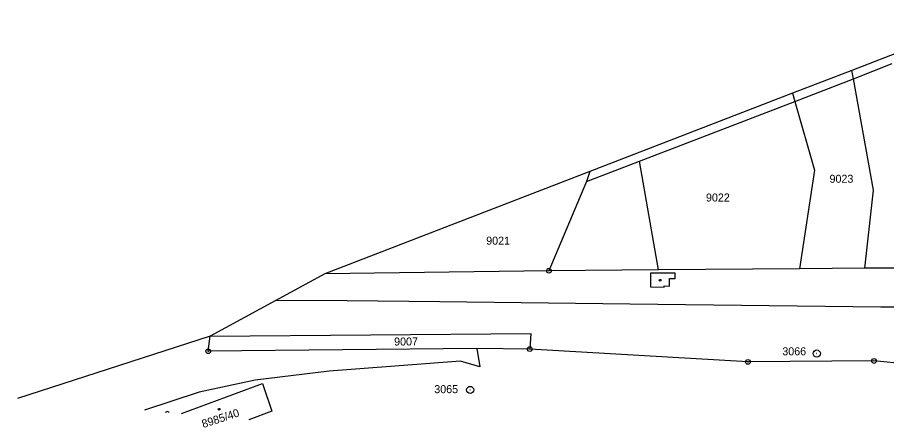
# Model space of a CAD drawing. Extents: x -825057 to -819383, y -1071633 to -1067888.
# Drawn here: x -825057.2 to -824872.6, y -1070106.1 to -1070019 of the extents above; entities that cross this region are included whole.
import ezdxf

# ---------------------------------------------------------------- set-up
doc = ezdxf.new("R2010")
doc.units = 0
for name, color, linetype in [('Vrstva 1', 7, 'Continuous'), ('Vrstva 10', 7, 'Continuous'), ('Vrstva 13', 7, 'Continuous'), ('Vrstva 17', 7, 'Continuous'), ('Vrstva 18', 7, 'Continuous'), ('Vrstva 19', 7, 'Continuous'), ('Vrstva 24', 7, 'Continuous'), ('Vrstva 25', 7, 'Continuous'), ('Vrstva 4', 7, 'Continuous')]:
    doc.layers.add(name, color=color, linetype=linetype)

msp = doc.modelspace()

# ---------------------------------------------------------------- linework, layer by layer
at = {"layer": 'Vrstva 1'}
for p, q in [((-824879.6, -1070032.03), (-824879.92, -1070030.25)), ((-824875.36, -1070055.66), (-824879.6, -1070032.03)), ((-824892.53, -1070035.09), (-824892.04, -1070036.81)), ((-824892.04, -1070036.81), (-824887.89, -1070051.42)), ((-824935.6, -1070051.67), (-824936.34, -1070053.81)), ((-824887.89, -1070051.42), (-824891.08, -1070072.35)), ((-824936.34, -1070053.81), (-824944.3, -1070072.78)), ((-824877.18, -1070072.24), (-824875.36, -1070055.66)), ((-824944.3, -1070072.78), (-824991.92, -1070073.41)), ((-824920.99, -1070072.59), (-824944.3, -1070072.78)), ((-824891.08, -1070072.35), (-824920.99, -1070072.59)), ((-824877.18, -1070072.24), (-824891.08, -1070072.35)), ((-824870.78, -1070072.19), (-824877.18, -1070072.24)), ((-825016.24, -1070086.67), (-824948.15, -1070086.08)), ((-824948.15, -1070086.08), (-824948.35, -1070089.4)), ((-825016.65, -1070089.86), (-825016.24, -1070086.67)), ((-824959.62, -1070089.3), (-825016.65, -1070089.86)), ((-824948.35, -1070089.4), (-824959.62, -1070089.3)), ((-824959.62, -1070089.3), (-824959, -1070093.16)), ((-824902.02, -1070092.13), (-824948.35, -1070089.4)), ((-824963.09, -1070091.99), (-824990.96, -1070094.07)), ((-824959, -1070093.16), (-824963.09, -1070091.99)), ((-824875.24, -1070091.93), (-824902.02, -1070092.13)), ((-824825.26, -1070096.77), (-824875.24, -1070091.93)), ((-824990.96, -1070094.07), (-825006.7, -1070095.98)), ((-825022.33, -1070103.09), (-825005.16, -1070096.71)), ((-825006.7, -1070095.98), (-825018.61, -1070098.58)), ((-825005.16, -1070096.71), (-825003.13, -1070102.57)), ((-825018.61, -1070098.58), (-825030.21, -1070102.38)), ((-825025.73, -1070102.78), (-825025.16, -1070102.57)), ((-825025.16, -1070102.57), (-825025.06, -1070102.84)), ((-825003.13, -1070102.57), (-825008.02, -1070104.39))]:
    msp.add_line(p, q, dxfattribs=at)
at = {"layer": 'Vrstva 10'}
for p, q in [((-824987.18, -1070079.15), (-825002.36, -1070079.1)), ((-824967.48, -1070079.36), (-824987.18, -1070079.15)), ((-824927.09, -1070079.84), (-824967.48, -1070079.36)), ((-824873.75, -1070080.47), (-824927.09, -1070079.84)), ((-824853.34, -1070080.66), (-824873.75, -1070080.47))]:
    msp.add_line(p, q, dxfattribs=at)
at = {"layer": 'Vrstva 13'}
for p, q in [((-824850.82, -1070018.98), (-824879.92, -1070030.25)), ((-824879.92, -1070030.25), (-824892.53, -1070035.09)), ((-824892.53, -1070035.09), (-824935.6, -1070051.67)), ((-824935.6, -1070051.67), (-824991.92, -1070073.41)), ((-824991.92, -1070073.41), (-825016.24, -1070086.67)), ((-825016.24, -1070086.67), (-825057.21, -1070099.92))]:
    msp.add_line(p, q, dxfattribs=at)
at = {"layer": 'Vrstva 24'}
for centre, radius in [((-824944.3, -1070072.78), 0.5), ((-824944.3, -1070072.78), 0.0327), ((-825016.65, -1070089.86), 0.5), ((-825016.65, -1070089.86), 0.0327), ((-824948.35, -1070089.4), 0.5), ((-824948.35, -1070089.4), 0.0327), ((-824887.38, -1070090.34), 0.75), ((-824902.02, -1070092.13), 0.5), ((-824887.38, -1070090.34), 0.0327), ((-824875.24, -1070091.93), 0.5), ((-824902.02, -1070092.13), 0.0327), ((-824875.24, -1070091.93), 0.0327), ((-824961.02, -1070098.06), 0.75), ((-824961.02, -1070098.06), 0.0327)]:
    msp.add_circle(centre, radius, dxfattribs=at)
at = {"layer": 'Vrstva 25'}
for centre in [(-824920.66, -1070074.78), (-825014.35, -1070102.16)]:
    msp.add_circle(centre, 0.175, dxfattribs=at)
at = {"layer": 'Vrstva 4'}
for p, q in [((-824879.6, -1070032.03), (-824871.35, -1070028.8)), ((-824892.04, -1070036.81), (-824879.6, -1070032.03)), ((-824925.04, -1070049.47), (-824892.04, -1070036.81)), ((-824936.34, -1070053.81), (-824925.04, -1070049.47)), ((-824920.99, -1070072.59), (-824925.04, -1070049.47)), ((-824922.68, -1070073.25), (-824922.71, -1070076.21)), ((-824917.48, -1070073.31), (-824922.68, -1070073.25)), ((-824918.67, -1070076.01), (-824918.65, -1070074.44)), ((-824918.65, -1070074.44), (-824917.49, -1070074.45)), ((-824917.49, -1070074.45), (-824917.48, -1070073.31)), ((-824922.71, -1070076.21), (-824919.8, -1070076.24)), ((-824919.8, -1070076.24), (-824919.8, -1070075.99)), ((-824919.8, -1070075.99), (-824918.67, -1070076.01))]:
    msp.add_line(p, q, dxfattribs=at)

# ---------------------------------------------------------------- texts
at = {"layer": 'Vrstva 17'}
for s, p in [('3066', (-824894.706, -1070090.72)), ('3065', (-824968.644, -1070098.76))]:
    msp.add_text(s, height=1.7, dxfattribs=at).set_placement(p)
at = {"layer": 'Vrstva 18'}
for s, p in [('9023', (-824884.678, -1070054.09)), ('9022', (-824910.926, -1070058.07)), ('9021', (-824957.614, -1070067.23)), ('9007', (-824977.174, -1070088.64))]:
    msp.add_text(s, height=1.7, dxfattribs=at).set_placement(p)
at = {"layer": 'Vrstva 19'}
msp.add_text('8985/40', height=1.7, rotation=18, dxfattribs=at).set_placement((-825017.715, -1070106.167))

doc.saveas('drawing.dxf')
